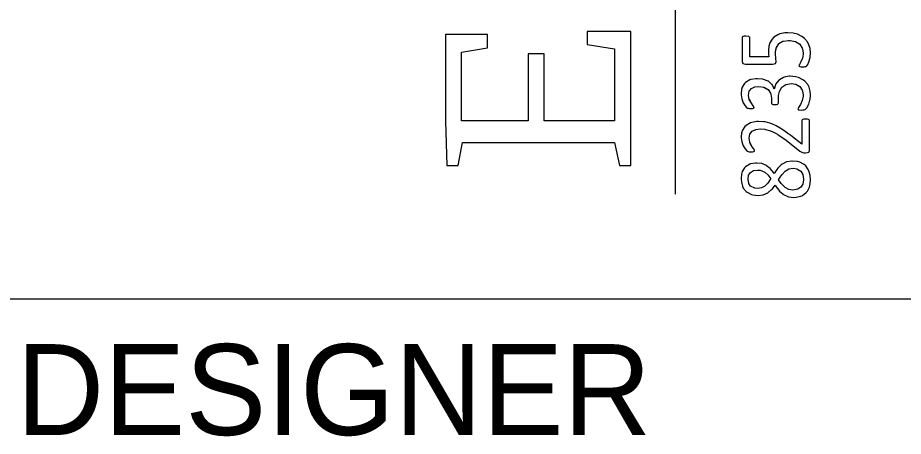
# Model space of a CAD drawing. Extents: x 0 to 43.6, y -18 to 22.
# Drawn here: x 32.051 to 33.026, y 2.349 to 2.809 of the extents above; entities that cross this region are included whole.
import ezdxf

# ---------------------------------------------------------------- set-up
doc = ezdxf.new("R2010")
doc.units = 0
for name, color, linetype in [('SH_Border', 7, 'Continuous'), ('SH_Data', 7, 'Continuous'), ('SH_Logo', 7, 'Continuous')]:
    doc.layers.add(name, color=color, linetype=linetype)

msp = doc.modelspace()

# ---------------------------------------------------------------- linework, layer by layer
at = {"layer": 'SH_Border'}
msp.add_line((32, 2.5), (33.5, 2.5), dxfattribs=at)
at = {"layer": 'SH_Logo'}
msp.add_line((32.77522, 2.61486), (32.77522, 4.25814), dxfattribs=at)
for points in [[(32.53608, 2.6467), (32.54064, 2.67178), (32.70809, 2.67178), (32.71341, 2.6467), (32.72599, 2.6467), (32.72599, 2.79414), (32.67811, 2.79414), (32.67811, 2.77953), (32.70817, 2.77497), (32.70817, 2.69576), (32.63049, 2.69576), (32.63049, 2.76931), (32.61292, 2.76931), (32.61292, 2.69576), (32.53988, 2.69576), (32.53988, 2.77142), (32.56825, 2.77606), (32.56825, 2.79059), (32.52206, 2.79059), (32.52206, 2.69542), (32.52358, 2.6467)], [(32.53988, 2.69576), (32.53988, 2.77142), (32.56825, 2.77606), (32.56825, 2.79059), (32.52206, 2.79059), (32.52206, 2.69542), (32.52358, 2.6467), (32.53608, 2.6467), (32.54064, 2.67178), (32.70809, 2.67178), (32.71341, 2.6467), (32.72599, 2.6467), (32.72599, 2.79414), (32.67811, 2.79414), (32.67811, 2.77953), (32.70817, 2.77497), (32.70817, 2.69576), (32.63049, 2.69576), (32.63049, 2.76931), (32.61292, 2.76931), (32.61292, 2.69576)], [(32.88517, 2.7587), (32.88589, 2.76047), (32.88557, 2.76425), (32.88557, 2.76449), (32.88525, 2.76907), (32.88533, 2.77156), (32.88605, 2.7759), (32.88629, 2.77654), (32.88878, 2.78055), (32.88878, 2.78063), (32.89328, 2.78337), (32.89392, 2.78353), (32.89963, 2.78425), (32.90139, 2.78417), (32.90678, 2.78312), (32.90726, 2.78296), (32.91176, 2.78023), (32.91208, 2.77991), (32.91457, 2.77581), (32.91489, 2.77477), (32.91553, 2.77019), (32.91545, 2.76891), (32.91473, 2.76449), (32.91312, 2.76047), (32.9116, 2.75782), (32.91095, 2.75646), (32.91111, 2.75589), (32.91184, 2.75541), (32.91312, 2.75517), (32.91489, 2.75509), (32.91666, 2.75517), (32.91786, 2.75533), (32.91875, 2.75557), (32.91947, 2.75605), (32.92059, 2.75766), (32.92196, 2.76079), (32.92316, 2.76521), (32.92324, 2.76577), (32.92365, 2.77043), (32.92324, 2.77517), (32.92196, 2.77943), (32.92027, 2.78272), (32.91714, 2.78642), (32.91425, 2.78859), (32.90935, 2.79092), (32.90461, 2.79212), (32.89874, 2.79252), (32.89537, 2.79236), (32.88991, 2.79132), (32.88758, 2.79043), (32.88316, 2.78762), (32.88139, 2.7857), (32.8789, 2.78144), (32.87778, 2.77774), (32.87738, 2.77292), (32.87746, 2.76915), (32.87778, 2.76601), (32.85697, 2.76601), (32.85697, 2.78722), (32.85585, 2.78843), (32.85263, 2.78891), (32.85071, 2.78883), (32.84942, 2.78843), (32.84862, 2.78786), (32.84838, 2.78714), (32.84838, 2.76087), (32.84926, 2.75887), (32.85207, 2.75814), (32.88228, 2.75814)], [(32.88139, 2.7857), (32.8789, 2.78144), (32.87778, 2.77774), (32.87738, 2.77292), (32.87746, 2.76915), (32.87778, 2.76601), (32.85697, 2.76601), (32.85697, 2.78722), (32.85585, 2.78843), (32.85263, 2.78891), (32.85071, 2.78883), (32.84942, 2.78843), (32.84862, 2.78786), (32.84838, 2.78714), (32.84838, 2.76087), (32.84926, 2.75887), (32.85207, 2.75814), (32.88228, 2.75814), (32.88517, 2.7587), (32.88589, 2.76047), (32.88557, 2.76425), (32.88557, 2.76449), (32.88525, 2.76907), (32.88533, 2.77156), (32.88611, 2.77624), (32.88878, 2.78055), (32.88878, 2.78063), (32.89328, 2.78337), (32.89392, 2.78353), (32.89963, 2.78425), (32.90139, 2.78417), (32.9071, 2.78306), (32.91196, 2.78011), (32.91457, 2.77581), (32.91489, 2.77477), (32.91553, 2.77019), (32.91545, 2.76891), (32.91473, 2.76449), (32.91312, 2.76047), (32.9116, 2.75782), (32.91095, 2.75646), (32.91111, 2.75589), (32.91184, 2.75541), (32.91312, 2.75517), (32.91489, 2.75509), (32.91666, 2.75517), (32.91786, 2.75533), (32.91875, 2.75557), (32.91947, 2.75605), (32.92059, 2.75766), (32.92196, 2.76079), (32.92316, 2.76521), (32.92324, 2.76577), (32.92365, 2.77043), (32.92324, 2.77517), (32.92196, 2.77943), (32.92027, 2.78272), (32.91714, 2.78642), (32.91425, 2.78859), (32.90935, 2.79092), (32.90461, 2.79212), (32.89874, 2.79252), (32.89537, 2.79236), (32.88991, 2.79132), (32.88758, 2.79043), (32.88316, 2.78762)], [(32.85504, 2.70946), (32.85625, 2.7093), (32.85778, 2.70922), (32.85978, 2.70938), (32.86099, 2.70954), (32.86155, 2.71002), (32.86171, 2.71051), (32.86067, 2.71211), (32.85858, 2.715), (32.85641, 2.71902), (32.85625, 2.71934), (32.85545, 2.72384), (32.85625, 2.72818), (32.85874, 2.73123), (32.86235, 2.733), (32.86677, 2.73356), (32.86685, 2.73356), (32.87248, 2.73276), (32.87689, 2.73019), (32.87697, 2.73011), (32.87971, 2.72609), (32.87995, 2.72521), (32.88067, 2.72063), (32.88067, 2.71541), (32.88083, 2.71468), (32.88147, 2.71412), (32.8826, 2.71372), (32.88444, 2.71364), (32.88637, 2.7138), (32.88758, 2.7142), (32.88822, 2.71476), (32.88846, 2.71557), (32.88846, 2.72135), (32.88854, 2.72352), (32.88943, 2.72786), (32.88975, 2.72874), (32.89224, 2.73276), (32.89224, 2.73276), (32.89657, 2.73573), (32.89674, 2.73573), (32.90228, 2.73669), (32.9075, 2.73597), (32.91176, 2.73348), (32.91457, 2.72954), (32.91481, 2.72874), (32.91553, 2.72408), (32.91545, 2.72272), (32.91457, 2.7183), (32.91449, 2.71806), (32.91256, 2.71372), (32.91063, 2.71051), (32.90975, 2.7089), (32.91055, 2.70794), (32.91336, 2.70761), (32.91537, 2.70769), (32.91682, 2.70786), (32.91778, 2.70818), (32.91859, 2.70874), (32.91987, 2.71043), (32.92156, 2.71372), (32.92164, 2.71388), (32.923, 2.71838), (32.92324, 2.71926), (32.92365, 2.72392), (32.92324, 2.72842), (32.92204, 2.73276), (32.92059, 2.73557), (32.91754, 2.73926), (32.91537, 2.74095), (32.91055, 2.74336), (32.90718, 2.74424), (32.90131, 2.74481), (32.90027, 2.74473), (32.89473, 2.74376), (32.89408, 2.74352), (32.88943, 2.74087), (32.88878, 2.74031), (32.88557, 2.73653), (32.88501, 2.73541), (32.88372, 2.73091), (32.88356, 2.73091), (32.8834, 2.73147), (32.88131, 2.73565), (32.88115, 2.73581), (32.8773, 2.73918), (32.87713, 2.73926), (32.87199, 2.74127), (32.87119, 2.74143), (32.86549, 2.742), (32.86356, 2.742), (32.85802, 2.74103), (32.85689, 2.74063), (32.85231, 2.7379), (32.85119, 2.73677), (32.84862, 2.73268), (32.84781, 2.73019), (32.84725, 2.72545), (32.84725, 2.72448), (32.84797, 2.71999), (32.84797, 2.7199), (32.84958, 2.71549), (32.85167, 2.71219), (32.8532, 2.71043), (32.85424, 2.70978)], [(32.8834, 2.73147), (32.88131, 2.73565), (32.88115, 2.73581), (32.8773, 2.73918), (32.87713, 2.73926), (32.87199, 2.74127), (32.87119, 2.74143), (32.86549, 2.742), (32.86356, 2.742), (32.85802, 2.74103), (32.85689, 2.74063), (32.85231, 2.7379), (32.85119, 2.73677), (32.84862, 2.73268), (32.84781, 2.73019), (32.84725, 2.72545), (32.84725, 2.72448), (32.848, 2.71984), (32.84958, 2.71549), (32.85167, 2.71219), (32.8532, 2.71043), (32.85424, 2.70978), (32.85504, 2.70946), (32.85625, 2.7093), (32.85778, 2.70922), (32.85978, 2.70938), (32.86099, 2.70954), (32.86155, 2.71002), (32.86171, 2.71051), (32.86067, 2.71211), (32.85858, 2.715), (32.85626, 2.71931), (32.85545, 2.72384), (32.85625, 2.72818), (32.85874, 2.73123), (32.86235, 2.733), (32.86681, 2.73357), (32.87248, 2.73276), (32.87694, 2.73016), (32.87971, 2.72609), (32.87995, 2.72521), (32.88067, 2.72063), (32.88067, 2.71541), (32.88083, 2.71468), (32.88147, 2.71412), (32.8826, 2.71372), (32.88444, 2.71364), (32.88637, 2.7138), (32.88758, 2.7142), (32.88822, 2.71476), (32.88846, 2.71557), (32.88846, 2.72135), (32.88854, 2.72352), (32.88943, 2.72786), (32.88975, 2.72874), (32.89224, 2.73276), (32.89657, 2.73573), (32.89674, 2.73573), (32.90228, 2.73669), (32.9075, 2.73597), (32.91176, 2.73348), (32.91457, 2.72954), (32.91481, 2.72874), (32.91553, 2.72408), (32.91545, 2.72272), (32.91455, 2.71819), (32.91256, 2.71372), (32.91063, 2.71051), (32.90975, 2.7089), (32.91055, 2.70794), (32.91336, 2.70761), (32.91537, 2.70769), (32.91682, 2.70786), (32.91778, 2.70818), (32.91859, 2.70874), (32.91987, 2.71043), (32.92156, 2.71372), (32.92164, 2.71388), (32.923, 2.71838), (32.92324, 2.71926), (32.92365, 2.72392), (32.92324, 2.72842), (32.92204, 2.73276), (32.92059, 2.73557), (32.91754, 2.73926), (32.91537, 2.74095), (32.91055, 2.74336), (32.90718, 2.74424), (32.90131, 2.74481), (32.90027, 2.74473), (32.89473, 2.74376), (32.89408, 2.74352), (32.88943, 2.74087), (32.88878, 2.74031), (32.88557, 2.73653), (32.88501, 2.73541), (32.88364, 2.73063)], [(32.85601, 2.67677), (32.85697, 2.68119), (32.85962, 2.68432), (32.86348, 2.68625), (32.86814, 2.68689), (32.87344, 2.68649), (32.87416, 2.68633), (32.87971, 2.68464), (32.88228, 2.6836), (32.88726, 2.68086), (32.88798, 2.68046), (32.89216, 2.67773), (32.89674, 2.67428), (32.912, 2.66239), (32.91336, 2.6615), (32.91473, 2.66086), (32.91626, 2.66062), (32.91826, 2.66054), (32.92035, 2.6607), (32.92172, 2.66118), (32.92236, 2.66207), (32.92252, 2.66311), (32.92252, 2.69589), (32.92228, 2.69669), (32.92148, 2.69725), (32.92019, 2.69757), (32.91834, 2.69765), (32.9165, 2.69757), (32.91521, 2.69717), (32.91441, 2.69661), (32.91417, 2.69589), (32.91417, 2.67002), (32.90196, 2.67942), (32.89866, 2.68191), (32.89433, 2.68504), (32.89031, 2.68761), (32.88581, 2.69018), (32.88123, 2.69235), (32.8789, 2.69315), (32.8736, 2.69444), (32.87223, 2.6946), (32.86653, 2.69492), (32.8646, 2.69492), (32.85906, 2.69388), (32.85753, 2.6934), (32.85296, 2.69074), (32.85159, 2.68946), (32.84878, 2.68536), (32.84781, 2.68255), (32.84725, 2.67781), (32.84725, 2.67717), (32.84797, 2.67267), (32.84797, 2.67259), (32.84958, 2.66817), (32.85167, 2.6648), (32.85328, 2.66287), (32.85432, 2.66215), (32.8552, 2.66183), (32.85625, 2.66167), (32.85778, 2.66158), (32.85986, 2.66175), (32.86123, 2.66199), (32.86195, 2.66239), (32.86219, 2.66303), (32.86123, 2.66472), (32.85906, 2.66761), (32.85697, 2.67163), (32.85673, 2.67219)], [(32.8736, 2.69444), (32.87223, 2.6946), (32.86653, 2.69492), (32.8646, 2.69492), (32.85906, 2.69388), (32.85753, 2.6934), (32.85296, 2.69074), (32.85159, 2.68946), (32.84878, 2.68536), (32.84781, 2.68255), (32.84725, 2.67781), (32.84725, 2.67717), (32.848, 2.67253), (32.84958, 2.66817), (32.85167, 2.6648), (32.85328, 2.66287), (32.85432, 2.66215), (32.8552, 2.66183), (32.85625, 2.66167), (32.85778, 2.66158), (32.85986, 2.66175), (32.86123, 2.66199), (32.86195, 2.66239), (32.86219, 2.66303), (32.86123, 2.66472), (32.85906, 2.66761), (32.85675, 2.67205), (32.85601, 2.67677), (32.85697, 2.68119), (32.85962, 2.68432), (32.86348, 2.68625), (32.86814, 2.68689), (32.87344, 2.68649), (32.87416, 2.68633), (32.87971, 2.68464), (32.88228, 2.6836), (32.88726, 2.68086), (32.88798, 2.68046), (32.89216, 2.67773), (32.89674, 2.67428), (32.912, 2.66239), (32.91336, 2.6615), (32.91473, 2.66086), (32.91626, 2.66062), (32.91826, 2.66054), (32.92035, 2.6607), (32.92172, 2.66118), (32.92236, 2.66207), (32.92252, 2.66311), (32.92252, 2.69589), (32.92228, 2.69669), (32.92148, 2.69725), (32.92019, 2.69757), (32.91834, 2.69765), (32.9165, 2.69757), (32.91521, 2.69717), (32.91441, 2.69661), (32.91417, 2.69589), (32.91417, 2.67002), (32.90196, 2.67942), (32.89866, 2.68191), (32.89433, 2.68504), (32.89031, 2.68761), (32.88581, 2.69018), (32.88123, 2.69235), (32.8789, 2.69315)], [(32.85384, 2.61708), (32.85866, 2.61467), (32.86027, 2.61419), (32.86597, 2.61355), (32.86605, 2.61355), (32.87167, 2.61427), (32.87665, 2.61652), (32.87697, 2.61676), (32.88091, 2.62005), (32.88171, 2.62094), (32.88469, 2.62495), (32.88589, 2.62311), (32.88878, 2.61925), (32.88959, 2.61837), (32.89344, 2.61507), (32.89392, 2.61467), (32.89882, 2.61234), (32.89955, 2.61218), (32.90525, 2.61146), (32.90774, 2.61154), (32.91312, 2.61282), (32.91473, 2.61355), (32.91891, 2.61668), (32.92027, 2.61845), (32.92244, 2.62279), (32.92324, 2.62624), (32.92365, 2.63098), (32.92332, 2.6354), (32.92236, 2.63973), (32.92124, 2.64231), (32.91842, 2.64616), (32.91682, 2.64753), (32.91208, 2.6501), (32.90935, 2.65082), (32.90348, 2.65146), (32.90308, 2.65146), (32.89754, 2.65058), (32.89714, 2.65042), (32.89232, 2.64793), (32.89151, 2.64729), (32.88782, 2.64367), (32.88653, 2.64198), (32.88372, 2.63789), (32.88292, 2.63901), (32.87971, 2.64279), (32.8793, 2.64319), (32.87529, 2.64632), (32.87513, 2.6464), (32.87015, 2.64857), (32.86452, 2.64929), (32.86332, 2.64929), (32.85778, 2.64833), (32.85673, 2.64801), (32.85223, 2.6452), (32.85111, 2.64399), (32.84862, 2.63982), (32.84773, 2.63684), (32.84725, 2.63202), (32.84757, 2.62809), (32.8487, 2.62383), (32.84974, 2.62174), (32.85271, 2.61805)], [(32.85778, 2.64833), (32.85673, 2.64801), (32.85223, 2.6452), (32.85111, 2.64399), (32.84862, 2.63982), (32.84773, 2.63684), (32.84725, 2.63202), (32.84757, 2.62809), (32.8487, 2.62383), (32.84974, 2.62174), (32.85271, 2.61805), (32.85384, 2.61708), (32.85866, 2.61467), (32.86027, 2.61419), (32.86597, 2.61355), (32.86605, 2.61355), (32.87167, 2.61427), (32.87665, 2.61652), (32.87697, 2.61676), (32.88091, 2.62005), (32.88171, 2.62094), (32.88469, 2.62495), (32.88589, 2.62311), (32.88878, 2.61925), (32.88959, 2.61837), (32.89344, 2.61507), (32.89392, 2.61467), (32.89882, 2.61234), (32.89955, 2.61218), (32.90525, 2.61146), (32.90774, 2.61154), (32.91312, 2.61282), (32.91473, 2.61355), (32.91891, 2.61668), (32.92027, 2.61845), (32.92244, 2.62279), (32.92324, 2.62624), (32.92365, 2.63098), (32.92332, 2.6354), (32.92236, 2.63973), (32.92124, 2.64231), (32.91842, 2.64616), (32.91682, 2.64753), (32.91208, 2.6501), (32.90935, 2.65082), (32.90348, 2.65146), (32.90308, 2.65146), (32.89754, 2.65058), (32.89714, 2.65042), (32.89232, 2.64793), (32.89151, 2.64729), (32.88782, 2.64367), (32.88653, 2.64198), (32.88372, 2.63789), (32.88292, 2.63901), (32.87971, 2.64279), (32.8793, 2.64319), (32.87529, 2.64632), (32.87513, 2.6464), (32.87015, 2.64857), (32.86452, 2.64929), (32.86332, 2.64929)], [(32.85496, 2.63138), (32.85561, 2.6358), (32.85778, 2.63893), (32.86107, 2.64086), (32.86549, 2.6415), (32.86846, 2.64126), (32.87344, 2.63909), (32.87681, 2.63612), (32.88003, 2.63194), (32.87946, 2.63114), (32.87657, 2.6272), (32.87328, 2.62391), (32.86958, 2.62198), (32.86549, 2.62134), (32.86227, 2.62166), (32.85778, 2.62391), (32.85585, 2.62656)], [(32.86107, 2.64086), (32.86549, 2.6415), (32.86846, 2.64126), (32.87344, 2.63909), (32.87681, 2.63612), (32.88003, 2.63194), (32.87946, 2.63114), (32.87657, 2.6272), (32.87328, 2.62391), (32.86958, 2.62198), (32.86549, 2.62134), (32.86227, 2.62166), (32.85778, 2.62391), (32.85585, 2.62656), (32.85496, 2.63138), (32.85561, 2.6358), (32.85778, 2.63893)], [(32.91593, 2.63162), (32.91593, 2.6309), (32.91513, 2.62608), (32.91296, 2.62254), (32.90983, 2.62046), (32.90429, 2.61941), (32.89971, 2.62013), (32.89569, 2.6223), (32.89569, 2.6223), (32.89208, 2.62584), (32.89135, 2.6268), (32.88846, 2.6309), (32.88951, 2.63251), (32.89208, 2.63644), (32.89232, 2.63668), (32.89569, 2.64038), (32.89971, 2.64271), (32.90453, 2.64343), (32.90846, 2.64295), (32.91288, 2.64046), (32.91312, 2.64022), (32.91529, 2.6366)], [(32.88846, 2.6309), (32.88951, 2.63251), (32.89208, 2.63644), (32.89232, 2.63668), (32.89569, 2.64038), (32.89971, 2.64271), (32.90453, 2.64343), (32.90846, 2.64295), (32.91303, 2.64038), (32.91529, 2.6366), (32.91593, 2.63162), (32.91593, 2.6309), (32.91513, 2.62608), (32.91296, 2.62254), (32.90983, 2.62046), (32.90429, 2.61941), (32.89971, 2.62013), (32.89569, 2.6223), (32.89208, 2.62584), (32.89135, 2.6268)]]:
    msp.add_lwpolyline(points, close=True, dxfattribs=at)
for points in [[(32.91682, 2.64753), (32.91208, 2.6501), (32.90935, 2.65082), (32.90348, 2.65146), (32.90308, 2.65146), (32.89754, 2.65058), (32.89714, 2.65042), (32.89232, 2.64793), (32.89151, 2.64729), (32.88782, 2.64367)], [(32.88846, 2.6309), (32.88951, 2.63251), (32.89208, 2.63644), (32.89232, 2.63668), (32.89569, 2.64038), (32.89971, 2.64271), (32.90453, 2.64343), (32.90846, 2.64295), (32.91288, 2.64046), (32.91312, 2.64022), (32.91529, 2.6366), (32.91593, 2.63162)]]:
    msp.add_lwpolyline(points, dxfattribs=at)

# ---------------------------------------------------------------- texts
at = {"layer": 'SH_Data'}
msp.add_text('DESIGNER', height=0.1, dxfattribs=at).set_placement((32.05, 2.35))

doc.saveas('drawing.dxf')
